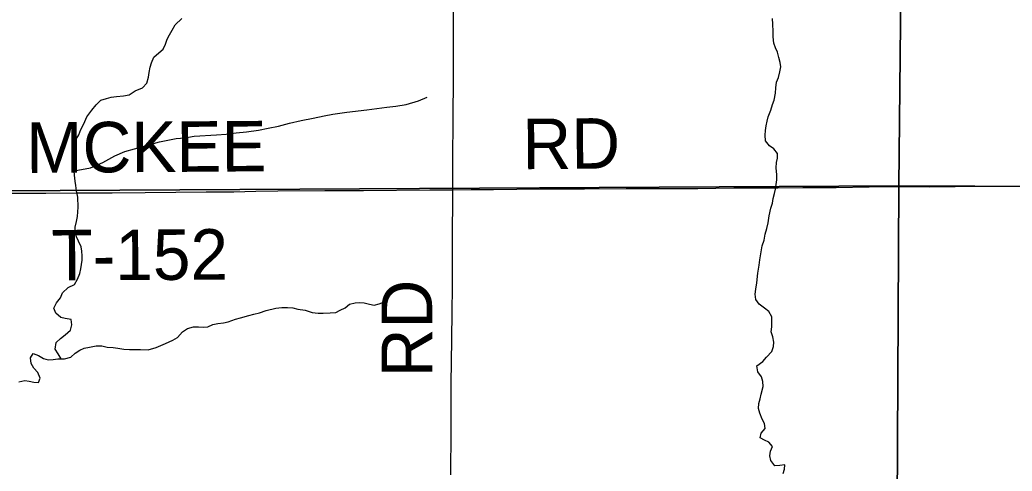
# Model space of a CAD drawing. Extents: x 1985906 to 2360102, y 891258 to 1222054.
# Drawn here: x 2087181 to 2093069, y 1002552 to 1005233 of the extents above; entities that cross this region are included whole.
import ezdxf

# ---------------------------------------------------------------- set-up
doc = ezdxf.new("R2010")
doc.units = 0
for name, color, linetype in [('GM_X_Minor_River', 7, 'Continuous'), ('GM_X_Section', 7, 'Continuous'), ('GM_X_Township_Road', 7, 'Continuous'), ('GM_X_Township_Road_Text', 7, 'Continuous')]:
    doc.layers.add(name, color=color, linetype=linetype)

msp = doc.modelspace()

# ---------------------------------------------------------------- linework, layer by layer
at = {"layer": 'GM_X_Minor_River'}
for points in [[(2087426.4, 1003219.5), (2087408.2, 1003249.5), (2087390, 1003277.5), (2087395.8, 1003315.7), (2087421.7, 1003339.9), (2087449.7, 1003362.1), (2087481.6, 1003390.4), (2087489.5, 1003422.5), (2087485.3, 1003452.6), (2087449.2, 1003458.5), (2087423.1, 1003464.4), (2087394.9, 1003490.4), (2087382.7, 1003520.4), (2087398.6, 1003552.6), (2087422.5, 1003582.8), (2087434.4, 1003611), (2087468.3, 1003643.3), (2087504.2, 1003661.5), (2087522.1, 1003693.7), (2087536, 1003725.9), (2087541.8, 1003754), (2087549.6, 1003806.2), (2087551.4, 1003832.3), (2087549.3, 1003858.4), (2087545.1, 1003884.5), (2087528.9, 1003918.6), (2087516.8, 1003944.6), (2087508.6, 1003970.7), (2087508.5, 1004000.8), (2087516.3, 1004034.9), (2087522.1, 1004065.1), (2087525.9, 1004121.3), (2087525.6, 1004179.5), (2087517.3, 1004217.6), (2087513.2, 1004249.7), (2087509, 1004275.8), (2087504.8, 1004309.9), (2087502.7, 1004336), (2087496.5, 1004364.1), (2087500.4, 1004394.2), (2087502.2, 1004422.3), (2087507.9, 1004486.6), (2087515.7, 1004524.8), (2087531.6, 1004550.9), (2087543.5, 1004581.1), (2087561.3, 1004615.3), (2087579.1, 1004657.6), (2087607, 1004695.8), (2087632.9, 1004728.1), (2087660.8, 1004756.3), (2087694.8, 1004766.5), (2087722.8, 1004774.6), (2087754.9, 1004776.8), (2087794.9, 1004781), (2087829, 1004787.2), (2087864.9, 1004811.4), (2087908.9, 1004829.7), (2087934.8, 1004857.9), (2087944.6, 1004892.1), (2087948.5, 1004920.2), (2087954.3, 1004952.3), (2087962.2, 1004978.5), (2087976.1, 1005010.7), (2088006, 1005036.9), (2088031.9, 1005059.1), (2088045.8, 1005089.3), (2088055.7, 1005117.4), (2088069.6, 1005143.6), (2088085.4, 1005171.8), (2088103.3, 1005203.9), (2088141.2, 1005240.2)], [(2091646.9, 1004730), (2091656.7, 1004756.1), (2091664.5, 1004798.3), (2091666.4, 1004828.4), (2091670.2, 1004862.6), (2091682.1, 1004890.8), (2091689.9, 1004924.9), (2091695.8, 1004953), (2091691.6, 1004979.1), (2091683.5, 1005009.2), (2091677.3, 1005041.3), (2091665.1, 1005067.3), (2091655, 1005095.4), (2091650.8, 1005131.5), (2091650.6, 1005163.6), (2091648.4, 1005207.8), (2091646.2, 1005241.9)], [(2087502.7, 1004336), (2087600.4, 1004353.8), (2087672.2, 1004386.2), (2087744, 1004424.7), (2087803.8, 1004451.1), (2087861.7, 1004467.4), (2088009.5, 1004508.3), (2088107.4, 1004528.9), (2088159.4, 1004533.2), (2088215.3, 1004541.6), (2088347.3, 1004550.3), (2088405.2, 1004554.7), (2088465.2, 1004561), (2088525.2, 1004567.4), (2088597.1, 1004577.8), (2088655, 1004590.2), (2088715, 1004602.5), (2088780.9, 1004618.9), (2088850.8, 1004635.3), (2088920.7, 1004649.8), (2088986.6, 1004662.2), (2089038.6, 1004672.5), (2089120.5, 1004685), (2089240.4, 1004697.7), (2089298.4, 1004706), (2089358.3, 1004714.4), (2089412.3, 1004720.7), (2089472.2, 1004731), (2089546.1, 1004751.5), (2089598, 1004773.8)], [(2091710.5, 1002538.1), (2091718.4, 1002564.2), (2091720.2, 1002590.3), (2091690.2, 1002586.2), (2091660.2, 1002584), (2091635.9, 1002616), (2091631.8, 1002644.1), (2091635.6, 1002672.2), (2091647.5, 1002698.4), (2091625.3, 1002724.4), (2091599.2, 1002736.3), (2091573.1, 1002750.2), (2091579, 1002778.4), (2091602.9, 1002806.6), (2091598.7, 1002834.7), (2091584.6, 1002860.7), (2091572.3, 1002896.8), (2091564.2, 1002924.8), (2091566, 1002955), (2091573.9, 1002981.1), (2091579.8, 1003009.2), (2091591.5, 1003055.5), (2091589.4, 1003085.6), (2091581.2, 1003113.6), (2091559, 1003141.6), (2091552.8, 1003177.7), (2091588.8, 1003204), (2091610.7, 1003230.2), (2091642.6, 1003262.5), (2091652.4, 1003292.6), (2091654.3, 1003318.7), (2091648.1, 1003350.8), (2091637.9, 1003380.9), (2091641.8, 1003409), (2091643.6, 1003441.1), (2091643.5, 1003469.2), (2091625.3, 1003501.3), (2091599.1, 1003521.2), (2091566.9, 1003545.2), (2091548.8, 1003571.2), (2091544.6, 1003603.3), (2091548.4, 1003633.4), (2091554.2, 1003671.6), (2091559.9, 1003727.8), (2091567.7, 1003776), (2091571.5, 1003808.2), (2091579.3, 1003854.4), (2091585.1, 1003890.6), (2091597, 1003924.7), (2091602.8, 1003960.9), (2091612.7, 1003993.1), (2091620.5, 1004027.2), (2091626.3, 1004069.4), (2091636.1, 1004113.6), (2091645.9, 1004143.8), (2091649.8, 1004171.9), (2091657.7, 1004202), (2091665.5, 1004228.2), (2091669.4, 1004254.3), (2091673.3, 1004282.4), (2091673.1, 1004312.5), (2091668.9, 1004354.7), (2091670.7, 1004384.8), (2091676.6, 1004410.9), (2091676.4, 1004439), (2091654.3, 1004467), (2091628.1, 1004485), (2091605.9, 1004515), (2091603.7, 1004549.1), (2091605.6, 1004575.2), (2091609.5, 1004603.3), (2091615.3, 1004631.5), (2091621.2, 1004657.6), (2091637, 1004695.8), (2091646.9, 1004730)], [(2088801.5, 1003522.8), (2088829.6, 1003514.9), (2088873.7, 1003509), (2088915.9, 1003495.2), (2088950, 1003491.3), (2088980, 1003491.4), (2089022.1, 1003493.7), (2089056.2, 1003495.8), (2089082.2, 1003508), (2089110.1, 1003522.1), (2089136.1, 1003544.3), (2089170.1, 1003552.5), (2089198.1, 1003554.7), (2089224.2, 1003552.8), (2089256.3, 1003544.9), (2089282.4, 1003539), (2089312.4, 1003547.1), (2089338.4, 1003555.3)], [(2087174.6, 1003083.8), (2087210.6, 1003090), (2087236.7, 1003086.1), (2087262.8, 1003080.2), (2087290.9, 1003078.3), (2087300.8, 1003104.5), (2087286.5, 1003138.5), (2087264.4, 1003164.5), (2087248.2, 1003192.6), (2087244, 1003224.7), (2087259.9, 1003250.9), (2087292, 1003239), (2087320.2, 1003221), (2087348.3, 1003213.1), (2087378.3, 1003215.2), (2087406.4, 1003219.4), (2087446.4, 1003219.6), (2087482.5, 1003229.8), (2087508.4, 1003254), (2087536.3, 1003270.2), (2087562.3, 1003282.3), (2087594.4, 1003288.5), (2087634.4, 1003296.7), (2087666.5, 1003296.8), (2087698.6, 1003289), (2087734.6, 1003287.1), (2087762.7, 1003283.2), (2087796.8, 1003277.4), (2087830.9, 1003275.5), (2087861, 1003275.6), (2087897, 1003275.8), (2087943.1, 1003274), (2087989.2, 1003286.3), (2088045.1, 1003310.6), (2088089.1, 1003330.9), (2088117.1, 1003347), (2088145, 1003379.3), (2088174.9, 1003399.5), (2088210.9, 1003409.7), (2088241, 1003409.8), (2088271.1, 1003408), (2088297.1, 1003410.1), (2088325.1, 1003424.3), (2088355.1, 1003430.4), (2088389.2, 1003432.6), (2088417.2, 1003438.7), (2088461.2, 1003455), (2088489.2, 1003463.2), (2088539.2, 1003477.4), (2088569.3, 1003485.6), (2088603.3, 1003493.8), (2088643.3, 1003506), (2088699.3, 1003520.3), (2088735.4, 1003524.5), (2088769.4, 1003524.6), (2088801.5, 1003522.8)]]:
    msp.add_lwpolyline(points, dxfattribs=at)
at = {"layer": 'GM_X_Section'}
for points in [[(2092452.1, 1009640.6), (2092396.2, 1004247.4), (2087061.4, 1004217.5), (2087071.5, 1009546.5)], [(2097869.4, 1009570.8), (2097809.3, 1004223.6), (2092396.2, 1004247.4), (2092452.1, 1009640.6)], [(2087061.4, 1004217.5), (2092396.2, 1004247.4), (2092369.4, 998903.3), (2087034.5, 998903.3)], [(2092396.2, 1004247.4), (2097809.3, 1004223.6), (2097790.4, 998905.6), (2092369.4, 998903.3)]]:
    msp.add_lwpolyline(points, close=True, dxfattribs=at)
at = {"layer": 'GM_X_Township_Road'}
for points in [[(2089750.2, 1004223.6), (2089750.1, 1004317.9), (2089749.7, 1004383.4), (2089750.9, 1004465.2), (2089751.9, 1004580), (2089752.3, 1004694.8), (2089754.1, 1004842.4), (2089754.7, 1004940.9), (2089754, 1005121.1), (2089753.6, 1005186.7), (2089754, 1005367.1)], [(2086228.5, 1004193.1), (2086253, 1004194.5), (2086269.3, 1004195.5), (2086318.3, 1004197.5), (2086482, 1004200.6), (2086645.8, 1004202.4), (2086727.7, 1004203.8), (2086809.7, 1004204.4), (2087154.1, 1004202.7), (2087334.5, 1004203.2), (2087515.1, 1004204.8), (2087728.3, 1004205.9), (2087925.3, 1004208.4), (2088105.6, 1004210.3), (2088285.8, 1004210.9), (2088449.5, 1004212.3), (2088580.4, 1004214.6), (2088711.5, 1004216.5), (2088990.3, 1004219.1), (2089219.9, 1004219.4), (2089613.6, 1004222.6), (2089744.6, 1004223.4), (2089750.2, 1004223.6)], [(2089738.2, 1002530.5), (2089739.6, 1002792.9), (2089740.1, 1003071.7), (2089744, 1003334), (2089745, 1003498), (2089747.3, 1003645.6), (2089748, 1003858.8), (2089748.8, 1003990), (2089750.4, 1004137.5), (2089750.2, 1004223.6)], [(2089750.2, 1004223.6), (2089859.5, 1004224.8), (2089990.6, 1004226.3), (2090269, 1004228.5), (2090400.2, 1004229.4), (2090531.4, 1004230.2), (2090777.5, 1004230.9), (2090974.4, 1004231.3), (2091089.3, 1004231.6), (2091204.1, 1004232), (2091416.9, 1004234.4), (2091515.2, 1004235.6), (2091679.2, 1004236.2), (2091826.9, 1004236.6), (2092023.8, 1004238.2), (2092220.4, 1004240.7), (2092416.9, 1004242.3), (2092578.4, 1004242.2), (2092729.8, 1004243.2), (2092826.9, 1004245), (2092941.7, 1004245.8), (2093384.4, 1004246.9)]]:
    msp.add_lwpolyline(points, dxfattribs=at)

# ---------------------------------------------------------------- texts
at = {"layer": 'GM_X_Township_Road_Text'}
for s, rotation, p in [('MCKEE', 0.39267, (2087219.1, 1004323.8)), ('RD', 0.4939, (2090164.1, 1004345.7)), ('T-152', 0.27935, (2087368.8, 1003685.1)), ('RD', 90, (2089627.4, 1003110.1))]:
    msp.add_text(s, height=300, rotation=rotation, dxfattribs=at).set_placement(p)

doc.saveas('drawing.dxf')
